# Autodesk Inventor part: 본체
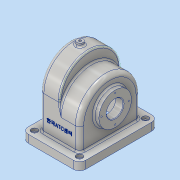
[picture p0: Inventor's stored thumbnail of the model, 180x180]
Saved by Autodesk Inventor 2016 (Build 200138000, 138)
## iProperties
Created: 2017-11
Part Number: 본체
Material: 알루미늄 6061
Document SubType Name: Modeling
Designer: 605-15
Mass: 1079.94 g
Surface Area: 1186.01 cm^2
Volume: 399.978 cm^3
Density: 2.7 g/cm^3
Appearance: 알루미늄 - 평지
Author: 605-15
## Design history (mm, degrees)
sketch "스케치1"
  geometry: L1 (55, -75)-(-55, -75); L2 (-55, -75)-(-55, 75); L3 (-55, 75)-(55, 75); L4 (55, 75)-(55, -75); L5 (55, -75)-(-55, 75); L6 (-55, -75)-(55, 75); 1 further point
  constraints: 12 end point, 2 midpoint, 2 parallel, 1 horizontal, 1 perpendicular
  dimensions: "d0" = 110 distance between parallel lines of L4 L2; "d1" = 150 distance of L3.end L1.start
extrude "돌출1" new body sketch "스케치1" distance "d2" = 15; taper "d3" = 0 deg
node "작업 평면1"
sketch "스케치2"
  geometry: 1 further point
sketch "스케치3"
  geometry: L1 (15, 0)-(15, 150) reference; L2 (15, 133)-(80, 133); L3 (80, 17)-(15, 17); C1 r 0.532 at (83.077, 71.826); A1 r 58 centre (80, 75) between (80, 17) and (80, 133); 1 further point
  constraints: 4 end point, 2 centre point, 2 point on circle, 2 point on line, 1 horizontal, 1 horizontal alignment, 1 parallel, 1 perpendicular, 1 tangent
  dimensions: "d5" = 80 distance of point (0, 75) A1.centre; "d6" = 58 radius of A1
extrude "돌출2" join sketch "스케치3" distance "d7" = 38; taper "d8" = 0 deg
sketch "스케치4"
  geometry: A1 r 58 centre (80, 75) between (80, 17) and (80, 133) reference; 1 further point
sketch "스케치5"
  geometry: L1 (0, 150)-(0, 0) reference; C1 r 37.5 at (65, 75); A1 r 58 centre (80, 75) between (80, 17) and (80, 133) reference; 1 further point
  constraints: 1 centre point, 1 horizontal alignment
  dimensions: "d9" = 65 distance from line of L1 C1.centre; "d10" = 75 diameter of C1
extrude "돌출3" join sketch "스케치5" distance "d11" = 9; taper "d12" = 0 deg
sketch "스케치6"
  geometry: L1 (-15, 17)-(-80, 17) reference; L2 (-80, 133)-(-15, 133) reference; L3 (0, 150)-(0, 0) reference; L4 (-15, 0)-(-15, 150) reference; L5 (-15, 17)-(-80, 17) reference; L6 (-57, 17)-(-15, 17); L7 (-80, 133)-(-15, 133) reference; L8 (-57, 133)-(-15, 133); L9 (-15, 17)-(-15, 133) reference; L10 (-15, 133)-(-15, 17); A1 r 58 centre (-57, 75) between (-57, 133) and (-57, 17); 2 further points
  constraints: 6 end point, 3 collinear, 2 point on circle, 2 point on line, 1 centre point, 1 horizontal alignment, 1 midpoint
  dimensions: "d13" = 57 distance from line of L3 A1.centre; "d14" = 116 diameter of A1
extrude "돌출4" join sketch "스케치6" distance "d15" = 38; taper "d16" = 0 deg
sketch "스케치7"
  geometry: L1 (0, 0)-(0, 150) reference; C1 r 31 at (-65, 75); 1 further point
  constraints: 1 centre point, 1 horizontal alignment
  dimensions: "d17" = 65 distance from line of L1 C1.centre; "d18" = 62 diameter of C1
extrude "돌출5" join sketch "스케치7" distance "d19" = 10; taper "d20" = 0 deg
node "작업 평면2"
sketch "스케치8"
  geometry: L1 (80, 128)-(0, 128); L2 (0, 150)-(0, 0) reference; L3 (80, 22)-(0, 22); A1 r 58 centre (80, 75) between (80, 17) and (80, 133) reference; A2 r 53 centre (80, 75) between (80, 22) and (80, 128); 1 further point
  constraints: 4 end point, 2 point on circle, 2 point on line, 1 centre point, 1 horizontal, 1 parallel
  dimensions: "d22" = 5 radial gap between concentric circles of A1 A2; "d23" = 53 distance of L1.end point (0, 75); "d24" = 53 distance of L3.end point (0, 75)
extrude "돌출6" cut sketch "스케치8" distance "d25" = 28; taper "d26" = 0 deg
sketch "스케치9"
  geometry: L1 (0, 150)-(0, 0) reference; L2 (57, 128)-(0, 128); L3 (57, 22)-(0, 22); A1 r 58 centre (57, 75) between (57, 17) and (57, 133) reference; A2 r 53 centre (57, 75) between (57, 22) and (57, 128); 1 further point
  constraints: 4 end point, 2 perpendicular, 2 point on circle, 2 point on line, 1 centre point
  dimensions: "d27" = 5 radial gap between concentric circles of A1 A2; "d28" = 53 distance of point (0, 75) L2.end; "d29" = 53 distance of L3.end point (0, 75)
extrude "돌출7" cut sketch "스케치9" distance "d30" = 38; taper "d31" = 0 deg
sketch "스케치10"
  geometry: 1 further point
hole "구멍1" diameter "d34" = 32; stored, may be unused: countersink angle "d38" = 90 deg, drill point angle "d40" = 118 deg; dims "d32" = 10, "d33" = 10, "d35" = 6, "d36" = 4, "d37" = 2, "d39" = 8
sketch "스케치11"
  geometry: 1 further point
sketch "스케치12"
  geometry: C1 r 37.5 at (0, 0) reference; 2 further points
  dimensions: "d41" = 29 distance of C1.centre point (29, 0)
hole "구멍2" sketch "스케치12" at (29, 0) diameter "d42" = 2.459; stored, may be unused: countersink angle "d46" = 90 deg, drill point angle "d48" = 118 deg; dims "d43" = 6, "d44" = 4, "d45" = 2, "d47" = 8
sketch "스케치13"
  geometry: C1 r 31 at (0, 0) reference; 2 further points
  constraints: 1 horizontal alignment
  dimensions: "d52" = 26 distance of C1.centre point (-26, 0)
hole "구멍3" sketch "스케치13" at (-26, 0) diameter "d53" = 2.459; stored, may be unused: countersink angle "d57" = 90 deg, drill point angle "d59" = 118 deg; dims "d54" = 6, "d55" = 4, "d56" = 2, "d58" = 8
node "작업 평면3"
sketch "스케치14"
  geometry: L1 (38, -58)-(38, 58) reference; C1 r 6 at (19, 0); 1 further point
  constraints: 1 centre point, 1 horizontal alignment
  dimensions: "d64" = 19 distance from line of L1 C1.centre; "d65" = 12 diameter of C1
extrude "돌출8" join sketch "스케치14" stored distance "d66" = 38; taper "d67" = 0 deg
hole "구멍4" diameter "d70" = 4.459; stored, may be unused: countersink angle "d74" = 90 deg, drill point angle "d76" = 118 deg; dims "d71" = 20, "d72" = 4, "d73" = 2, "d75" = 8, "d89" = 10, "d90" = 10
fillet "모깎기1" dims "d77" = 8
fillet "모깎기2" dims "d78" = 3
fillet "모깎기3" dims "d79" = 3
chamfer "모따기1" distance "d80" = 1; stored, may be unused: second distance "d81" = 2, angle "d82" = 45 deg
fillet "모깎기4" dims "d83" = 3
fillet "모깎기5" dims "d84" = 3
sketch "스케치15"
  geometry: 1 further point
sketch "스케치16"
  geometry: L1 (-25, -18)-(85, -18) reference; L2 (-8, 62)-(-8, 0) reference; 2 further points
  constraints: 1 other
  dimensions: "d85" = 40 distance from line of L1 point (30, 22); "d86" = 38 distance from line of point (30, 22) L2
feature "엠보싱1" sketch "스케치16" dims "d87" = 0.5, "d88" = 0
fillet "모깎기6" dims "d91" = 12
sketch "스케치17"
  geometry: A1 r 12 centre (-43, -63) between (-55, -63) and (-43, -75) reference; A2 r 12 centre (-43, 63) between (-43, 75) and (-55, 63) reference; A3 r 12 centre (43, 63) between (55, 63) and (43, 75) reference; A4 r 12 centre (43, -63) between (43, -75) and (55, -63) reference; 5 further points
  constraints: 4 coincident
hole "구멍5" sketch "스케치17" at (-43, -63), (-43, 63), (43, 63), (43, -63) diameter "d92" = 5; stored, may be unused: countersink angle "d96" = 90 deg, drill point angle "d98" = 118 deg; dims "d93" = 6, "d94" = 12, "d95" = 5, "d97" = 8
node "솔리드1"
pattern_circular "원형 패턴1" dims angle "d50" = 360 deg
pattern_circular "원형 패턴2" dims angle "d61" = 360 deg
other parameters: "d4" = -55, "d21" = -5, "d63" = -144
